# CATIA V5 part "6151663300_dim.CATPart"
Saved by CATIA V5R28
Part number: 6151663300_dim
Source: made
Property "PROI_CREATED_ON": "12/17/2008 9:21:37 AM"
Property "BLANK_DRAWING": "--"
Property "DRAWN_BY": "ALG"
Property "FINISH": "--"
Property "HEAT_TREATMENT": "ASSIGN"
Property "MATERIAL": "ASSIGN"
Property "PROJECT": "--"
Property "PROTOTYPE_NO": "--"
Property "RELATED_DRAWING": "--"
Property "COMPLETE_MATERIAL": "ASSIGN-ASSIGN"
Property "DESCRIPTION": "EABCLRT110-1300 eLink"
Property "DRAWING_EXIST": "--"
Property "MANUFACTURER": "--"
Property "MANUFACTURER_2": "--"
Property "MANUFACTURER_REF": "--"
Property "TYPE_PART": "A"
Property "TODAY_DATE": "2026/02/09"
Property "PDMREV": "01.0"
Property "PDMRL": "Production"
Property "PROI_REVISION": "01"
Property "PROI_VERSION": "0"
Property "PROI_RELEASE": "Production"
Property "PTC_MODIFIED": false
Property "MFG_WP_MATERIAL": "ASSIGN"
Property "COMPANY_CODE": "---"
Property "DESCRIPTION_JP": "--"
Property "PQP_DOCUMENT": "--"
Property "SUPPLIER": "--"
Property "REFERENCE": "6151663300"
Property "PTC_WM_REVISION": "01"
Property "PTC_WM_ITERATION": "0"
Property "PTC_WM_VERSION": "01.0"
Property "PTC_WM_LIFECYCLE_STATE": "Production"
Property "PTC_WM_LIFECYCLE": "Design_Process"
Property "PTC_WM_LOCATION": "/Products/BATTERY TOOLS/A3320 - EABLRT/9-01-Dimensional Drawings and 3D"
Property "PTC_WM_CREATED_BY": "Alain Le Goc (grealg) (grealg: CPD)"
Property "PTC_WM_CREATED_ON": "09-Feb-26 03:21:37 PM"
Property "PTC_WM_MODIFIED_BY": "Alain Le Goc (grealg) (grealg: CPD)"
Property "PTC_WM_MODIFIED_ON": "09-Feb-26 04:26:31 PM"
Property "PTC_WM_TEAM": "Default"
Property "PTC_ORGANIZATION_ID": "CPD"
Property "PTC_WM_NAME": "6151663300_dim.prt"
Property "PTC_WM_NUMBER": "6151663300_DIM.PRT"
Property "PTC_COMMON_NAME": "6151663300_dim.prt"
Property "PTC_MASTER_MATERIAL": "ASSIGN"
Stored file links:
  d:\ptc\Echange\temp\6151663300_dim.CATPart

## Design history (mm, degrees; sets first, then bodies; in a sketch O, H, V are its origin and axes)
AxisSystem1 "CS0": origin (0, 0, 0), X (1, 0, 0), Y (0, 1, 0), Z (0, 0, 1)
Set1
  DatumSurface1 "Sheet.1"
  DatumSurface2 "Sheet.2"
  DatumSurface3 "Sheet.3"
  DatumSurface4 "Sheet.4"
  DatumSurface5 "Sheet.5"
  DatumSurface6 "Sheet.6"
  DatumSurface7 "Sheet.7"
  DatumSurface8 "Sheet.8"
  DatumSurface9 "Sheet.9"
  DatumSurface10 "Sheet.10"
  DatumSurface11 "Sheet.11"
  DatumSurface12 "Sheet.12"
  DatumSurface13 "Sheet.13"
  DatumSurface14 "Sheet.14"
  DatumSurface15 "Sheet.15"
  DatumSurface16 "Sheet.16"
  DatumSurface17 "Sheet.17"
  DatumSurface18 "Sheet.18"
  DatumSurface19 "Sheet.19"
  DatumSurface20 "Sheet.20"
  DatumSurface21 "Sheet.21"
  DatumSurface22 "Sheet.22"
  DatumSurface23 "Sheet.23"
  DatumSurface24 "Sheet.24"
  DatumSurface25 "Sheet.25"
  DatumSurface26 "Sheet.26"
  DatumSurface27 "Sheet.27"
  DatumSurface28 "Sheet.28"
  DatumSurface29 "Sheet.29"
  DatumSurface30 "Sheet.30"
  DatumSurface31 "Sheet.31"
  DatumSurface32 "Sheet.32"
  DatumSurface33 "Sheet.33"
  DatumSurface34 "Sheet.34"
  DatumSurface35 "Sheet.35"
  DatumSurface36 "Sheet.36"
  DatumSurface37 "Sheet.37"
  Plane1 "RIGHT": stored without definition
  Plane2 "TOP": stored without definition
  Plane3 "FRONT": stored without definition
Body1 "PartBody" (main body)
